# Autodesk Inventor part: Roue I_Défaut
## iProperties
Shininess: 64.0
Length Units: 11269
Angle Units: 11279
Time Units: 11290
Mass Units: 11283
Length Display Precision: 3
Angle Display Precision: 2
Compacted: True
Part Number: Roue I_Défaut
Document SubType Name: Modeling
Created: 2006-01
Material: Par défaut
Designer: Fricot
Density: 0.0
Volumn: 0.0
Area: 0.0
PropertySet Name: Model Information
Control State: 0
Master: False
Checked Out: False
Author: Fricot
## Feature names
1. Base1
